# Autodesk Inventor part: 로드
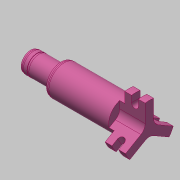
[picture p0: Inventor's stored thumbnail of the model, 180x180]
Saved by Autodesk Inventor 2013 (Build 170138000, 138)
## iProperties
Created: 2020-02
Part Number: 로드
Material: 강철, 연강
Document SubType Name: Modeling
Designer: mduedu
Density: 1 g/cm^3
Author: mduedu
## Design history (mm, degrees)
sketch "스케치1"
  geometry: L1 (0, 0)-(-12, 0); L2 (-12, 0)-(-12, 15); L3 (-12, 15)-(0, 15); L4 (0, 15)-(0, 0); L5 (-12, 0)-(-52, 0); L6 (-52, 0)-(-52, 9); L7 (-52, 9)-(-12, 9); L8 (-12, 9)-(-12, 0); L9 (-52, 0)-(-70, 0); L10 (-70, 0)-(-70, 6); L11 (-70, 6)-(-52, 6); L12 (-52, 6)-(-52, 0)
  constraints: 24 end point, 6 parallel, 3 horizontal, 3 perpendicular
  dimensions: "d0" = 70 distance between parallel lines of L4 L10; "d2" = 18 distance of L10.end L11.end; "d3" = 40 distance of L6.end L7.end; "d4" = 12 diameter of L11 L9; "d5" = 18 diameter of L7 L5; "d6" = 30 diameter of L3 L1
revolve "회전1" sketch "스케치1" stored, may be unused: angle "d7" = 90 deg
chamfer "모따기1" distance "d8" = 1.4; stored, may be unused: second distance "d9" = 2, angle "d10" = 15 deg
fillet "모깎기1" dims "d11" = 3
chamfer "모따기2" distance "d12" = 1.4; stored, may be unused: second distance "d13" = 2, angle "d14" = 15 deg
fillet "모깎기2" dims "d15" = 3
sketch "스케치2"
  geometry: L1 (50.981, 8.898)-(52, 8.625) reference; L2 (52, 8.625)-(52, 6) reference; L3 (52, 6)-(68.205, 6) reference; L4 (68.981, 5.898)-(70, 5.625) reference; L5 (70, 5.625)-(70, -5.625) reference; L6 (70, -5.625)-(68.981, -5.898) reference; L7 (68.205, -6)-(52, -6) reference; L8 (52, -6)-(52, -8.625) reference; L9 (52, -8.625)-(50.981, -8.898) reference; L10 (50.205, -9)-(12, -9) reference; L11 (12, -9)-(12, -15) reference; L12 (12, -15)-(0, -15) reference; L13 (0, -15)-(0, 15) reference; L14 (0, 15)-(12, 15) reference; L15 (12, 15)-(12, 9) reference; L16 (12, 9)-(50.205, 9) reference; L17 (0, 0)-(70, 0); L18 (65, 6)-(66.15, 6); L19 (66.15, 6)-(66.15, 5.75); L20 (66.15, 5.75)-(65, 5.75); L21 (65, 5.75)-(65, 6); A1 r 3 centre (50.205, 6) between (50.981, 8.898) and (50.205, 9) reference; A2 r 3 centre (68.205, 3) between (68.981, 5.898) and (68.205, 6) reference; A3 r 3 centre (68.205, -3) between (68.205, -6) and (68.981, -5.898) reference; A4 r 3 centre (50.205, -6) between (50.205, -9) and (50.981, -8.898) reference
  constraints: 10 end point, 2 parallel, 1 horizontal, 1 midpoint, 1 perpendicular, 1 point on line
  dimensions: "d16" = 13 distance between parallel lines of L21 L2; "d17" = 1.15 distance of L18.start L18.end; "d18" = 11.5 diameter of L20 L17
revolve "회전2" sketch "스케치2" stored, may be unused: angle "d19" = 90 deg
sketch "스케치3"
  geometry: L1 (0, 0)-(-15, 0); L2 (0, 0)-(7.5, -12.99); L3 (0, 0)-(7.5, 12.99); L4 (-1.443, -2.5)-(-14.79, -2.5); L5 (-1.443, 2.5)-(-14.79, 2.5); L6 (-1.443, -2.5)-(5.23, -14.059); L7 (2.887, 0)-(9.56, -11.559); L8 (2.887, 0)-(9.56, 11.559); L9 (-1.443, 2.5)-(5.23, 14.059); C1 r 15 at (0, 0) reference; 1 further point
  constraints: 18 end point, 6 parallel, 1 coincident, 1 horizontal, 15 other
  dimensions: "d20" = 120 deg angle of L2 L1; "d21" = 120 deg angle of L3 L1; "d22" = 5 distance between parallel lines of L5 L4; "d24" = 5 distance between parallel lines of L7 L6; "d25" = 5 distance between parallel lines of L9 L8
extrude "돌출1" cut sketch "스케치3" distance "d26" = 15; taper "d27" = 0 deg
fillet "모깎기3" dims "d28" = 5
sketch "스케치4"
  geometry: L1 (4, 21)-(8, 21); L2 (8, 21)-(8, 11); L3 (8, 11)-(4, 11); L4 (4, 11)-(4, 21); 2 further points
  constraints: 8 end point, 2 parallel, 1 horizontal, 1 horizontal alignment, 1 midpoint, 1 perpendicular, 2 other
  dimensions: "d29" = 11 distance from line of L3 point (0, 0); "d30" = 4 distance of L1.start L1.end; "d31" = 6 horizontal distance of point (6, 11) point (0, 0); "d32" = 10 distance between parallel lines of L1 L3
extrude "돌출2" cut sketch "스케치4" stored distance "d33" = 15; taper "d34" = 0 deg
node "솔리드1"
pattern_circular "원형 패턴1" dims angle "d36" = 360 deg
node "투영된 루프1"
node "절단 모서리 투영1"
